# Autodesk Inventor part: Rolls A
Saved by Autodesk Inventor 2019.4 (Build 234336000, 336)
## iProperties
Created: 2020-05
Part Number: Rolls A
Material: Generic
Document SubType Name: Modeling
Designer: Administrator
Density: 1 g/cm^3
Appearance: Default
Title: Rolls A
Author: Administrator
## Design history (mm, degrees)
feature "Body1"
feature "Body2"
feature "Body3"
feature "Body4"
feature "Body21"
feature "Body22"
feature "Body23"
feature "Body24"
feature "Body25"
feature "Body26"
feature "Body29"
feature "Body30"
feature "Body31"
body "Solid1"
body "Solid2"
body "Solid3"
body "Solid4"
body "Solid5"
body "Solid6"
body "Solid7"
body "Solid8"
body "Solid9"
body "Solid10"
body "Solid11"
body "Solid12"
body "Solid13"
